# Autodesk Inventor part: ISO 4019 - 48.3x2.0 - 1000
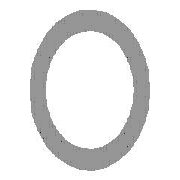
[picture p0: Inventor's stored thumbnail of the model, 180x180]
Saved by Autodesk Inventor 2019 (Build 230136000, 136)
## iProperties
IsCustomPart: 1
Created: 2018-01
Part Number: ISO 4019 - 48.3x2.0 - 1000
Material: Acier, doux
Description: Aciers de construction - Coupes creuses profilées formées à froid, soudées
Document SubType Name: Modeling
Standard: ISO
Designer: Fabian Perrée
Standard Revision: Second edition 2001-09-01
Standards Organization: ISO
Language: fr-FR
Size Designation: 48.3x2.0
Categories: <MemberInstance><Categories><Category DisplayName="Profilés" InternalName="089c4875-fa83-4c05-b084-43b9cc11f5ed" Mnemonic="GRDR"><CategoryParameter DisplayName=
Stock Number: 48.3x2.0
Density: 7.85 g/cm^3
Appearance: Semi-poli
Mass: 2169.32 g
Surface Area: 2784.02 cm^2
Volume: 276.347 cm^3
_CCFamilyMember: 14
_CCFamilyDisplayName: ISO 4019 (Profils creux circulaires - Formés à froid) - Aciers de construction - Coupes creuses profilées formées à froid, soudées — ISO 4019 (Profils creux cir
_FrameMemberDoc: Frame Member File
_Version: 15.0.0
_GetPNFromCC: 1
G_L: 1000,000 mm
G_W: 48,300 mm
G_H: 48,300 mm
+6CF9212D-CCC1-49D6-9294-5D3E9515860C+DETAILDECOUPE1: Grugeage
+010BC43A-D804-4444-9BAD-6047175C2C4F+DETAILDECOUPE2: Grugeage
Author: Fabian Perrée
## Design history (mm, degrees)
node "Plan de départ"
node "Plan de fin"
sketch "Esquisse"
  geometry: C1 r 22.15 at (0, 0); C2 r 24.15 at (0, 0); 2 further points
  constraints: 3 coincident, 2 centre point
  dimensions: "d0" = 48.3 diameter of C2 (= G_H); "d1" = 2 radial gap between concentric circles of C2 C1 (= G_T)
extrude "Corps" new body sketch "Esquisse" stored distance "d2" = 1000 (= G_L); taper "d3" = 0 deg
node "Driven Length"
  sketch "Sketch3"
    geometry: L1 (0, 0)-(10, 0) reference
    constraints: 2 end point, 1 horizontal
  workplane "Work Plane3"
  sketch "Sketch4"
    geometry: L1 (-2, 0)-(12, 0) reference; L2 (-2, 1000)-(12, 1000) reference
    dimensions: "d7" = 1000 distance between parallel lines of L1 L2 (derived)
body "Solid1"
feature "Sculpter1"
feature "Combiner1"
feature "Sculpter3"
feature "Combiner3"
body "Srf5"
body "Srf6"
node "Solide3"
body "Srf11"
body "Srf12"
node "Solide5"
feature "Surface1"
body "Srf4"
feature "Carreau délimité3" dims "d12" = 5, "d13" = 0
feature "Carreau délimité4" dims "d14" = 5, "d15" = 0
feature "Surface3"
body "Srf10"
feature "Carreau délimité7" dims "d20" = 5, "d21" = 0
feature "Carreau délimité8" dims "d22" = 5, "d23" = 0
other parameters: "G_H" = 48.3 [user parameter; used in 1 equation term], "G_T" = 2 [user parameter; used in 1 equation term], "G_L" = 1000 (= d7) [user parameter; used in 1 equation term], "G_OFFSET_START" = 0 [user parameter; used in 1 equation term], "G_OFFSET_END" = 0 [user parameter; used in 1 equation term], "d4" = 0 (computed from G_OFFSET_START), "d6" = 90 deg, "MAS" = 0.228 [user parameter]
